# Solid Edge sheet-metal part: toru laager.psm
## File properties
Title: toru laager
Author: Stella-Marii
Template: iso metric sheet metal.psm
Last saved by: Stella-Marii
Revision: 6
Application: Solid Edge
Document Number: 39
Density: 7833,000 kg/m^3
Accuracy: 0,990
Material Thickness: 2,00 mm
Bend Radius: 1,00 mm
Relief Width: 1,00 mm
Relief Length: 0,00 mm
Neutral Factor: 0,330
Minimum Arc Length: 0,10 mm
Deviational Tolerance: 0,10 mm
Username: Stella-Marii
Material: Steel, structural
Face Style: Steel
Fill Style: ANSI32(Steel)
Virtual Style: Brushed steel
Grouping: Metals\Steel
LibraryName: Materials
Coef. of Thermal Exp: 1.3e-05
Thermal Conductivity: 32.0
Specific Heat: 481.0
Modulus of Elasticity: 199947953000.0
Poisson's Ratio: 0.29
Yield Stress: 262000766.0
Ultimate Stress: 358527364.0
Elongation: 0.0
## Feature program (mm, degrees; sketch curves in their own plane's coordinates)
base tab "unnamed BaseTab 1"
sketch for "Hole_1" plane through (0, 0, 2) normal (0, 0, 1) x-axis (1, 0, 0)
  hole centre (0, 0) bore radius 11.25
hole "Hole_1"
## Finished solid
Body 1: solid body, 4 faces, 4 edges, 0 vertices.
  Faces by surface: cylinder 2, plane 2
  Edges by curve: circle 4
Bounding box of the edges (mm): 47.000 x 47.000 x 2.000, from (-23.5, -23.5, 0) to (23.5, 23.5, 2).
Cylindrical faces by radius (mm): R11.25 x1, R23.5 x1
Planar faces by outward normal: +z 1, -z 1
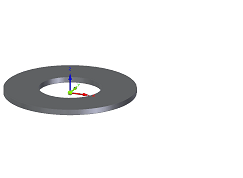
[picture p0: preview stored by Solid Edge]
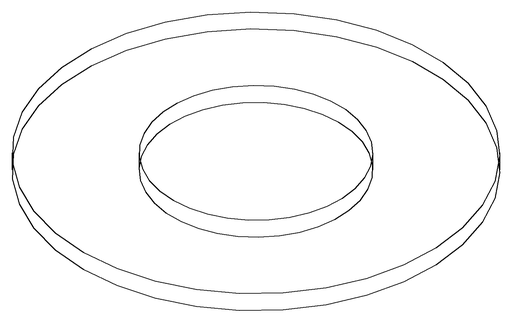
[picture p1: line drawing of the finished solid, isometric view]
